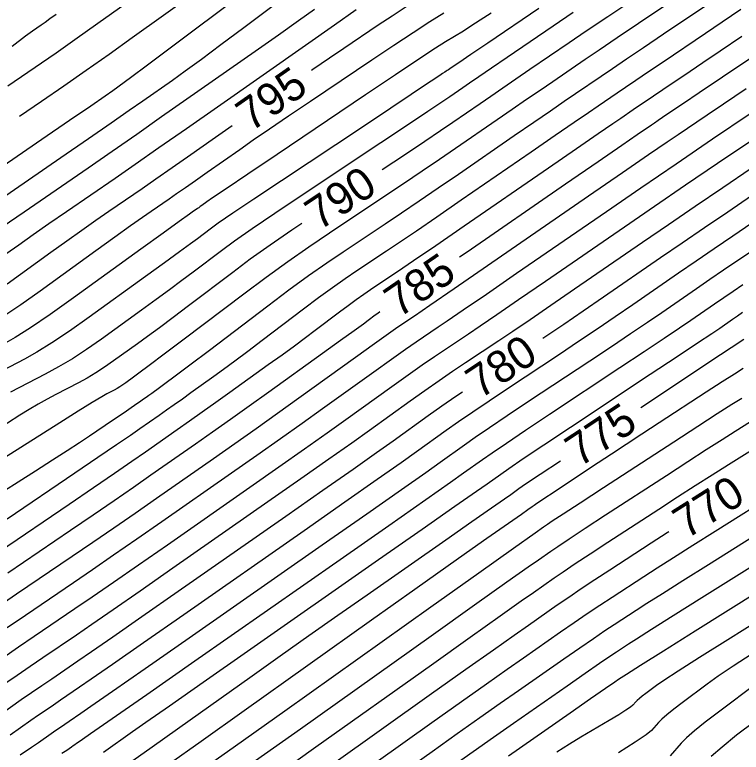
# Model space of a CAD drawing. Extents: x 2079879 to 2092887, y 778083 to 784051.
# Drawn here: x 2084522.6 to 2084585.7, y 781189.1 to 781253.2 of the extents above; entities that cross this region are included whole.
import ezdxf

# ---------------------------------------------------------------- set-up
doc = ezdxf.new("R2010")
doc.units = 0
doc.layers.add('DT_X_Contour_Major', color=7, linetype='Continuous')
doc.layers.add('DT_X_Contour_Minor', color=7, linetype='Continuous')

msp = doc.modelspace()

# ---------------------------------------------------------------- linework, layer by layer
at = {"layer": 'DT_X_Contour_Major'}
for points in [[(2084538.211, 781255.129), (2084532.768, 781251.231), (2084530.745, 781249.789), (2084528.757, 781248.387), (2084526.805, 781247.025), (2084524.887, 781245.702), (2084522.969, 781244.387)], [(2084576.341, 781254.591), (2084574.085, 781253.065), (2084572.219, 781251.8), (2084570.743, 781250.797), (2084567.327, 781248.469), (2084566.096, 781247.629), (2084564.961, 781246.854), (2084563.925, 781246.144), (2084562.987, 781245.498), (2084560.614, 781243.864), (2084559.565, 781243.147), (2084558.195, 781242.223), (2084556.505, 781241.091), (2084554.496, 781239.752), (2084554.491, 781239.749)], [(2084594.669, 781254.961), (2084586.708, 781249.594), (2084584.046, 781247.799), (2084582.028, 781246.439), (2084580.657, 781245.514), (2084579.93, 781245.024), (2084578.853, 781244.298), (2084578.477, 781244.044), (2084578.157, 781243.827), (2084577.892, 781243.647), (2084577.682, 781243.505), (2084577.197, 781243.174), (2084576.636, 781242.789), (2084575.319, 781241.883), (2084573.246, 781240.454), (2084570.415, 781238.504), (2084561.859, 781232.609), (2084561.215, 781232.165)], [(2084611.07, 781254.745), (2084608.274, 781252.74), (2084607.173, 781251.948), (2084605.967, 781251.077), (2084604.656, 781250.126), (2084603.241, 781249.096), (2084599.326, 781246.242), (2084597.779, 781245.129), (2084596.074, 781243.929), (2084594.21, 781242.642), (2084592.187, 781241.268), (2084586.582, 781237.488), (2084584.512, 781236.088), (2084582.503, 781234.724), (2084580.557, 781233.394), (2084578.673, 781232.1), (2084573.731, 781228.695), (2084571.936, 781227.463), (2084570.257, 781226.32), (2084568.695, 781225.267), (2084568.44, 781225.097)], [(2084556.664, 781253.975), (2084555.338, 781253.122), (2084554.145, 781252.331), (2084551.141, 781250.306), (2084549.91, 781249.47), (2084548.469, 781248.479), (2084548.334, 781248.385)], [(2084541.448, 781243.574), (2084539.722, 781242.364), (2084537.868, 781241.067), (2084536.233, 781239.926), (2084534.818, 781238.943), (2084533.622, 781238.116), (2084530.727, 781236.123), (2084529.598, 781235.339), (2084528.384, 781234.485), (2084527.083, 781233.561), (2084525.697, 781232.565), (2084521.887, 781229.816)], [(2084547.501, 781235.091), (2084546.632, 781234.506), (2084544.737, 781233.197), (2084543.026, 781231.977), (2084541.498, 781230.845), (2084537.667, 781227.946), (2084536.313, 781226.925), (2084535.122, 781226.034), (2084534.094, 781225.273), (2084533.23, 781224.644), (2084531.145, 781223.139), (2084530.367, 781222.597), (2084529.6, 781222.1), (2084528.842, 781221.648), (2084528.094, 781221.241), (2084526.113, 781220.215), (2084525.361, 781219.815), (2084524.592, 781219.382), (2084523.804, 781218.917), (2084522.999, 781218.42), (2084520.828, 781217.052)], [(2084554.29, 781227.41), (2084554.105, 781227.274), (2084553.883, 781227.109), (2084553.271, 781226.645), (2084552.851, 781226.336), (2084552.051, 781225.756), (2084550.871, 781224.906), (2084549.311, 781223.784), (2084544.644, 781220.432), (2084542.932, 781219.206), (2084541.295, 781218.041), (2084539.734, 781216.938), (2084538.249, 781215.897), (2084534.389, 781213.202), (2084532.866, 781212.144), (2084531.195, 781210.992), (2084529.374, 781209.745), (2084527.403, 781208.403), (2084521.95, 781204.698)], [(2084585.925, 781225.016), (2084584.799, 781224.269), (2084582.963, 781223.051), (2084580.418, 781221.364), (2084576.974, 781219.081)], [(2084561.451, 781220.438), (2084560.893, 781220.058), (2084559.657, 781219.199), (2084558.481, 781218.364), (2084555.427, 781216.17), (2084553.986, 781215.144), (2084551.955, 781213.712), (2084549.333, 781211.873), (2084546.121, 781209.628), (2084536.769, 781203.099), (2084533.593, 781200.884), (2084531.08, 781199.136), (2084529.231, 781197.855), (2084528.045, 781197.041), (2084525.767, 781195.493), (2084524.903, 781194.904), (2084524.02, 781194.297), (2084523.117, 781193.671), (2084522.196, 781193.027), (2084519.711, 781191.285), (2084518.71, 781190.592), (2084517.569, 781189.82), (2084516.289, 781188.969)], [(2084569.974, 781214.439), (2084568.203, 781213.26), (2084566.951, 781212.421), (2084566.358, 781212.015), (2084565.655, 781211.51), (2084565.104, 781211.121), (2084563.979, 781210.332), (2084562.279, 781209.143), (2084560.004, 781207.555), (2084553.172, 781202.785), (2084550.626, 781201.004), (2084548.112, 781199.237), (2084545.63, 781197.485), (2084543.18, 781195.748), (2084536.689, 781191.133), (2084534.505, 781189.581), (2084532.824, 781188.386)], [(2084579.393, 781208.293), (2084579.259, 781208.207), (2084577.866, 781207.305), (2084574.274, 781204.969), (2084572.978, 781204.12), (2084571.784, 781203.326), (2084570.692, 781202.587), (2084569.7, 781201.902), (2084567.193, 781200.15), (2084565.962, 781199.285), (2084564.15, 781198.004), (2084561.757, 781196.307), (2084558.783, 781194.194), (2084550.077, 781188.005)], [(2084591.899, 781203.525), (2084584.532, 781198.9), (2084582.071, 781197.35), (2084580.216, 781196.17), (2084578.965, 781195.359), (2084578.318, 781194.917), (2084577.402, 781194.232), (2084577.089, 781193.993), (2084576.838, 781193.792), (2084576.649, 781193.628), (2084576.523, 781193.5), (2084576.267, 781193.21), (2084576.068, 781193.046), (2084575.661, 781192.773), (2084575.046, 781192.389), (2084574.223, 781191.896), (2084571.753, 781190.435), (2084570.766, 781189.832), (2084569.656, 781189.119)]]:
    msp.add_lwpolyline(points, dxfattribs=at)
at = {"layer": 'DT_X_Contour_Minor'}
for points in [[(2084545.551, 781257.468), (2084538.269, 781251.987), (2084535.833, 781250.156), (2084533.986, 781248.771), (2084532.729, 781247.833), (2084532.061, 781247.342), (2084531.065, 781246.629), (2084530.4, 781246.163), (2084529.152, 781245.3), (2084527.32, 781244.04), (2084524.906, 781242.382), (2084517.691, 781237.434)], [(2084548.153, 781256.39), (2084542.461, 781252.106), (2084540.472, 781250.616), (2084538.775, 781249.357), (2084537.369, 781248.331), (2084536.255, 781247.536), (2084533.671, 781245.726), (2084532.501, 781244.909), (2084530.927, 781243.818), (2084528.95, 781242.453), (2084526.57, 781240.813), (2084519.686, 781236.072)], [(2084583.912, 781254.906), (2084578.934, 781251.546), (2084577.196, 781250.372), (2084575.714, 781249.37), (2084574.488, 781248.539), (2084573.518, 781247.88), (2084571.275, 781246.351), (2084570.312, 781245.693), (2084569.105, 781244.865), (2084567.653, 781243.868), (2084565.958, 781242.701), (2084561.112, 781239.362), (2084559.351, 781238.152), (2084557.702, 781237.029), (2084556.166, 781235.991), (2084554.742, 781235.038), (2084551.095, 781232.613), (2084549.66, 781231.637), (2084548.09, 781230.528), (2084546.386, 781229.285), (2084544.548, 781227.91), (2084539.467, 781224.064), (2084537.767, 781222.779), (2084536.48, 781221.809), (2084535.606, 781221.153), (2084535.143, 781220.812), (2084534.461, 781220.322), (2084534.21, 781220.143), (2084533.971, 781219.972), (2084533.743, 781219.811), (2084533.525, 781219.659), (2084532.961, 781219.264), (2084532.682, 781219.071), (2084532.268, 781218.788), (2084531.72, 781218.414), (2084531.038, 781217.951), (2084529.04, 781216.593), (2084528.185, 781216.022), (2084527.121, 781215.329), (2084525.846, 781214.512), (2084524.362, 781213.572), (2084520.124, 781210.901)], [(2084568.085, 781253.794), (2084563.655, 781250.775), (2084562.195, 781249.781), (2084561.14, 781249.063), (2084560.49, 781248.622), (2084560.244, 781248.457), (2084560.126, 781248.386), (2084560.053, 781248.339), (2084559.921, 781248.252), (2084559.732, 781248.126), (2084559.485, 781247.959), (2084558.749, 781247.463), (2084558.173, 781247.078), (2084556.998, 781246.295), (2084555.225, 781245.115), (2084552.852, 781243.537), (2084545.726, 781238.798), (2084543.335, 781237.204), (2084541.508, 781235.975), (2084540.245, 781235.11), (2084539.545, 781234.611), (2084538.429, 781233.767), (2084537.834, 781233.324), (2084536.884, 781232.63), (2084535.58, 781231.684), (2084533.922, 781230.486), (2084529.029, 781226.955), (2084527.301, 781225.733), (2084525.785, 781224.715), (2084524.482, 781223.9), (2084523.392, 781223.289), (2084520.769, 781221.931)], [(2084548.598, 781253.704), (2084547.207, 781252.7), (2084545.486, 781251.477), (2084543.434, 781250.033), (2084537.522, 781245.89), (2084535.321, 781244.351), (2084533.154, 781242.842), (2084531.021, 781241.363), (2084528.921, 781239.914), (2084523.367, 781236.089), (2084521.462, 781234.775)], [(2084578.961, 781253.962), (2084576.769, 781252.481), (2084574.899, 781251.217), (2084573.353, 781250.169), (2084572.131, 781249.338), (2084569.301, 781247.41), (2084568.204, 781246.661), (2084567.033, 781245.86), (2084565.789, 781245.006), (2084564.472, 781244.099), (2084560.863, 781241.613), (2084559.458, 781240.65), (2084557.949, 781239.626), (2084556.336, 781238.541), (2084554.619, 781237.395), (2084549.902, 781234.259), (2084548.111, 781233.046), (2084546.276, 781231.759), (2084544.397, 781230.397), (2084542.474, 781228.962), (2084537.286, 781225.036), (2084535.552, 781223.725), (2084534.241, 781222.736), (2084533.351, 781222.068), (2084532.884, 781221.723), (2084532.202, 781221.23), (2084531.948, 781221.053), (2084531.697, 781220.891), (2084531.449, 781220.743), (2084531.204, 781220.61), (2084530.557, 781220.274), (2084530.119, 781220.023), (2084529.292, 781219.519), (2084528.076, 781218.763), (2084526.471, 781217.754), (2084521.672, 781214.73)], [(2084532.141, 781254.164), (2084529.779, 781252.477), (2084527.78, 781251.057), (2084526.143, 781249.906), (2084524.869, 781249.022), (2084521.953, 781247.023)], [(2084563.943, 781253.381), (2084562.998, 781252.753), (2084562.198, 781252.234), (2084561.543, 781251.825), (2084559.989, 781250.88), (2084559.119, 781250.327), (2084557.672, 781249.375), (2084555.648, 781248.025), (2084553.048, 781246.277), (2084545.347, 781241.085), (2084542.8, 781239.367), (2084540.935, 781238.108), (2084539.752, 781237.308), (2084539.25, 781236.966), (2084538.822, 781236.666), (2084538.671, 781236.56), (2084538.537, 781236.467), (2084538.421, 781236.387), (2084538.324, 781236.319), (2084538.087, 781236.156), (2084537.734, 781235.904), (2084536.854, 781235.271), (2084535.447, 781234.257), (2084533.511, 781232.861), (2084527.647, 781228.63), (2084525.619, 781227.187), (2084523.93, 781226.033), (2084522.583, 781225.167), (2084521.575, 781224.59)], [(2084559.853, 781253.375), (2084558.621, 781252.609), (2084557.168, 781251.675), (2084555.493, 781250.574), (2084553.597, 781249.304), (2084548.244, 781245.696), (2084546.355, 781244.419), (2084544.702, 781243.294), (2084543.285, 781242.321), (2084542.105, 781241.5), (2084539.272, 781239.515), (2084538.269, 781238.813), (2084537.385, 781238.197), (2084536.62, 781237.665), (2084535.973, 781237.218), (2084534.407, 781236.139), (2084533.666, 781235.622), (2084532.619, 781234.878), (2084531.265, 781233.909), (2084529.604, 781232.713), (2084524.767, 781229.223), (2084523.094, 781228.033), (2084521.701, 781227.081)], [(2084552.236, 781253.664), (2084550.353, 781252.347), (2084547.815, 781250.569), (2084540.172, 781245.214), (2084537.467, 781243.32), (2084535.081, 781241.656), (2084533.016, 781240.221), (2084531.272, 781239.015), (2084527.047, 781236.106), (2084525.53, 781235.057), (2084524.148, 781234.093), (2084522.902, 781233.213), (2084521.79, 781232.417)], [(2084585.655, 781253.684), (2084584.042, 781252.595), (2084582.585, 781251.612), (2084578.907, 781249.13), (2084577.623, 781248.263), (2084576.528, 781247.522), (2084575.622, 781246.908), (2084574.906, 781246.421), (2084573.249, 781245.292), (2084572.42, 781244.725), (2084571.176, 781243.871), (2084569.517, 781242.73), (2084567.444, 781241.302), (2084561.361, 781237.111), (2084559.244, 781235.655), (2084557.456, 781234.432), (2084555.996, 781233.44), (2084554.865, 781232.681), (2084552.287, 781230.967), (2084551.273, 781230.277), (2084550.163, 781229.493), (2084548.959, 781228.615), (2084547.66, 781227.643), (2084544.068, 781224.925), (2084542.795, 781223.965), (2084541.671, 781223.125), (2084540.694, 781222.404), (2084539.866, 781221.803), (2084537.855, 781220.359), (2084537.118, 781219.83), (2084536.412, 781219.329), (2084535.74, 781218.853), (2084535.1, 781218.405), (2084533.437, 781217.244), (2084532.615, 781216.675), (2084531.397, 781215.841), (2084529.784, 781214.74), (2084527.774, 781213.374), (2084521.887, 781209.375)], [(2084571.084, 781253.431), (2084569.355, 781252.255), (2084565.354, 781249.529), (2084563.987, 781248.597), (2084562.89, 781247.848), (2084562.061, 781247.281), (2084561.501, 781246.897), (2084560.365, 781246.115), (2084559.672, 781245.644), (2084558.441, 781244.82), (2084556.675, 781243.641), (2084554.372, 781242.109), (2084547.517, 781237.551), (2084545.152, 781235.967), (2084543.197, 781234.636), (2084541.654, 781233.556), (2084540.521, 781232.728), (2084538.048, 781230.857), (2084537.073, 781230.125), (2084536.003, 781229.332), (2084534.837, 781228.479), (2084533.576, 781227.565), (2084530.087, 781225.047), (2084528.801, 781224.148), (2084527.559, 781223.338), (2084526.362, 781222.619), (2084525.209, 781221.989), (2084522.195, 781220.428)], [(2084526.139, 781253.249), (2084525.614, 781252.876), (2084525.184, 781252.574), (2084524.85, 781252.342), (2084524.084, 781251.817), (2084523.502, 781251.382), (2084522.33, 781250.471)], [(2084585.735, 781251.338), (2084583.842, 781250.062), (2084582.349, 781249.055), (2084581.257, 781248.318), (2084578.88, 781246.714), (2084578.05, 781246.153), (2084577.342, 781245.674), (2084576.757, 781245.278), (2084576.294, 781244.963), (2084575.223, 781244.233), (2084574.528, 781243.757), (2084573.248, 781242.877), (2084571.382, 781241.592), (2084568.929, 781239.903), (2084561.61, 781234.86), (2084559.137, 781233.158), (2084557.209, 781231.835), (2084555.826, 781230.89), (2084554.988, 781230.325), (2084553.479, 781229.321), (2084552.886, 781228.918), (2084552.237, 781228.459), (2084551.532, 781227.945), (2084550.771, 781227.376), (2084548.669, 781225.785), (2084547.823, 781225.151), (2084546.861, 781224.441), (2084545.783, 781223.655), (2084544.589, 781222.793), (2084541.25, 781220.395), (2084540.025, 781219.518), (2084538.854, 781218.685), (2084537.737, 781217.896), (2084536.674, 781217.151), (2084533.913, 781215.223), (2084532.721, 781214.396), (2084531.218, 781213.363), (2084529.402, 781212.122), (2084527.275, 781210.675), (2084521.186, 781206.539)], [(2084586.118, 781246.797), (2084584.15, 781245.47), (2084582.723, 781244.508), (2084581.839, 781243.912), (2084580.204, 781242.809), (2084579.256, 781242.164), (2084577.641, 781241.057), (2084575.357, 781239.487), (2084572.405, 781237.454), (2084563.642, 781231.417), (2084560.744, 781229.421), (2084558.624, 781227.962), (2084557.28, 781227.039), (2084556.713, 781226.653), (2084556.238, 781226.338), (2084555.851, 781226.069), (2084555.046, 781225.496), (2084553.822, 781224.621), (2084552.18, 781223.443), (2084547.244, 781219.898), (2084545.392, 781218.573), (2084543.538, 781217.255), (2084541.682, 781215.945), (2084539.823, 781214.643), (2084534.865, 781211.181), (2084533.012, 781209.892), (2084531.172, 781208.62), (2084529.345, 781207.367), (2084527.532, 781206.13), (2084522.713, 781202.857), (2084520.886, 781201.611)], [(2084586.469, 781244.628), (2084583.197, 781242.417), (2084580.024, 781240.261), (2084576.949, 781238.16), (2084573.972, 781236.116), (2084566.164, 781230.737), (2084563.542, 781228.932), (2084561.532, 781227.552), (2084560.134, 781226.596), (2084559.347, 781226.065), (2084558.066, 781225.216), (2084557.436, 781224.787), (2084556.508, 781224.137), (2084555.281, 781223.266), (2084553.755, 781222.173), (2084549.29, 781218.966), (2084547.541, 781217.716), (2084545.642, 781216.369), (2084543.595, 781214.927), (2084541.398, 781213.389), (2084535.341, 781209.161), (2084533.157, 781207.64), (2084531.149, 781206.249), (2084529.317, 781204.989), (2084527.66, 781203.858), (2084523.477, 781201.016), (2084521.89, 781199.934)], [(2084586.507, 781242.248), (2084583.636, 781240.307), (2084580.85, 781238.415), (2084578.151, 781236.572), (2084575.539, 781234.777), (2084568.686, 781230.056), (2084566.34, 781228.442), (2084564.44, 781227.141), (2084562.987, 781226.153), (2084561.981, 781225.478), (2084559.893, 781224.094), (2084559.021, 781223.505), (2084557.969, 781222.777), (2084556.739, 781221.91), (2084555.331, 781220.904), (2084551.335, 781218.034), (2084549.689, 781216.859), (2084547.746, 781215.484), (2084545.508, 781213.909), (2084542.972, 781212.136), (2084535.817, 781207.14), (2084533.302, 781205.388), (2084531.126, 781203.878), (2084529.288, 781202.611), (2084527.788, 781201.586), (2084524.24, 781199.175), (2084522.894, 781198.257), (2084521.519, 781197.311)], [(2084586.545, 781239.868), (2084584.074, 781238.198), (2084581.677, 781236.569), (2084579.354, 781234.983), (2084577.106, 781233.439), (2084571.208, 781229.376), (2084569.138, 781227.953), (2084567.349, 781226.731), (2084565.841, 781225.71), (2084564.615, 781224.89), (2084561.72, 781222.971), (2084560.605, 781222.223), (2084559.431, 781221.418), (2084558.198, 781220.554), (2084556.906, 781219.634), (2084553.381, 781217.102), (2084551.838, 781216.002), (2084549.851, 781214.598), (2084547.42, 781212.891), (2084544.547, 781210.882), (2084536.293, 781205.119), (2084533.448, 781203.136), (2084531.103, 781201.507), (2084529.26, 781200.233), (2084527.917, 781199.313), (2084525.004, 781197.334), (2084523.899, 781196.581), (2084522.769, 781195.804), (2084521.615, 781195.003)], [(2084586.62, 781235.108), (2084584.95, 781233.979), (2084583.33, 781232.878), (2084581.759, 781231.806), (2084580.239, 781230.762), (2084576.253, 781228.015), (2084574.734, 781226.974), (2084573.165, 781225.91), (2084571.548, 781224.824), (2084569.882, 781223.715), (2084565.375, 781220.727), (2084563.775, 781219.66), (2084562.355, 781218.698), (2084561.116, 781217.843), (2084560.056, 781217.094), (2084557.472, 781215.238), (2084556.135, 781214.287), (2084554.059, 781212.826), (2084551.246, 781210.855), (2084547.696, 781208.374), (2084537.244, 781201.078), (2084533.738, 781198.631), (2084531.058, 781196.764), (2084529.203, 781195.477), (2084528.174, 781194.769), (2084526.531, 781193.653), (2084525.908, 781193.227), (2084525.271, 781192.789), (2084524.62, 781192.338), (2084523.955, 781191.873), (2084522.163, 781190.617)], [(2084586.658, 781232.728), (2084585.388, 781231.869), (2084584.156, 781231.032), (2084582.962, 781230.217), (2084581.806, 781229.423), (2084578.775, 781227.335), (2084577.531, 781226.484), (2084576.074, 781225.5), (2084574.402, 781224.38), (2084572.516, 781223.127), (2084567.202, 781219.605), (2084565.36, 781218.378), (2084563.817, 781217.339), (2084562.574, 781216.488), (2084561.632, 781215.824), (2084559.518, 781214.306), (2084558.283, 781213.43), (2084556.163, 781211.941), (2084553.159, 781209.837), (2084549.27, 781207.12), (2084537.72, 781199.057), (2084533.883, 781196.379), (2084531.035, 781194.393), (2084529.174, 781193.099), (2084528.302, 781192.496), (2084527.294, 781191.812), (2084526.912, 781191.551), (2084526.521, 781191.282), (2084526.122, 781191.005), (2084525.714, 781190.72), (2084524.615, 781189.95), (2084524.008, 781189.537), (2084523.013, 781188.876)], [(2084585.826, 781229.76), (2084584.982, 781229.187), (2084584.165, 781228.628), (2084583.373, 781228.085), (2084581.297, 781226.654), (2084580.329, 781225.995), (2084578.982, 781225.089), (2084577.256, 781223.937), (2084575.15, 781222.539), (2084569.03, 781218.482), (2084566.945, 781217.096), (2084565.279, 781215.979), (2084564.033, 781215.132), (2084563.207, 781214.555), (2084561.564, 781213.374), (2084560.431, 781212.573), (2084558.268, 781211.055), (2084555.072, 781208.819), (2084550.845, 781205.867), (2084538.196, 781197.036), (2084534.029, 781194.127), (2084531.012, 781192.022), (2084529.146, 781190.721), (2084528.431, 781190.224), (2084528.058, 781189.971), (2084527.916, 781189.874), (2084527.772, 781189.775), (2084527.624, 781189.672), (2084527.473, 781189.567), (2084527.067, 781189.282), (2084526.658, 781189.009)], [(2084585.809, 781227.341), (2084585.367, 781227.04), (2084584.94, 781226.746), (2084583.819, 781225.974), (2084583.127, 781225.506), (2084581.89, 781224.679), (2084580.109, 781223.494), (2084577.784, 781221.952), (2084570.857, 781217.36), (2084568.529, 781215.814), (2084566.741, 781214.62), (2084565.492, 781213.777), (2084564.782, 781213.285), (2084563.609, 781212.442), (2084562.69, 781211.793), (2084560.811, 781210.476), (2084557.973, 781208.491), (2084554.176, 781205.839), (2084542.771, 781197.877), (2084538.94, 781195.202), (2084536.001, 781193.146), (2084533.952, 781191.71), (2084532.795, 781190.894), (2084530.26, 781189.092)], [(2084585.851, 781222.497), (2084585.091, 781222.007), (2084584.02, 781221.313), (2084582.639, 781220.415), (2084578.541, 781217.749), (2084577.058, 781216.782), (2084575.684, 781215.883), (2084574.417, 781215.051), (2084573.259, 781214.285), (2084570.315, 781212.334), (2084569.338, 781211.686), (2084568.616, 781211.205), (2084568.147, 781210.892), (2084567.933, 781210.745), (2084567.7, 781210.578), (2084567.518, 781210.45), (2084567.146, 781210.189), (2084566.584, 781209.796), (2084565.832, 781209.27), (2084563.573, 781207.693), (2084562.312, 781206.807), (2084560.224, 781205.329), (2084557.308, 781203.26), (2084553.565, 781200.601), (2084542.48, 781192.721), (2084538.751, 781190.07), (2084535.881, 781188.029)], [(2084585.724, 781219.891), (2084584.868, 781219.348), (2084583.602, 781218.533), (2084581.924, 781217.447), (2084579.834, 781216.089), (2084573.715, 781212.108), (2084571.69, 781210.79), (2084570.205, 781209.821), (2084569.259, 781209.202), (2084568.854, 781208.932), (2084568.492, 781208.679), (2084567.779, 781208.174), (2084565.91, 781206.847), (2084562.887, 781204.698), (2084558.708, 781201.727), (2084546.024, 781192.711), (2084541.734, 781189.661), (2084538.375, 781187.273)], [(2084587.829, 781218.683), (2084585.147, 781216.999), (2084584.02, 781216.285), (2084582.649, 781215.408), (2084581.035, 781214.367), (2084579.178, 781213.161), (2084573.901, 781209.728), (2084572.119, 781208.567), (2084570.731, 781207.656), (2084569.737, 781206.997), (2084569.136, 781206.589), (2084568.059, 781205.836), (2084567.173, 781205.211), (2084565.324, 781203.899), (2084562.51, 781201.901), (2084558.733, 781199.216), (2084547.375, 781191.143), (2084543.482, 781188.375)], [(2084588.201, 781216.386), (2084584.57, 781214.106), (2084583.171, 781213.223), (2084581.697, 781212.283), (2084580.147, 781211.287), (2084578.522, 781210.233), (2084574.088, 781207.349), (2084572.549, 781206.343), (2084571.258, 781205.491), (2084570.214, 781204.792), (2084569.418, 781204.246), (2084567.626, 781202.993), (2084566.568, 781202.248), (2084564.737, 781200.951), (2084562.134, 781199.104), (2084558.758, 781196.705), (2084548.726, 781189.574), (2084545.23, 781187.089)], [(2084588.945, 781211.792), (2084583.417, 781208.321), (2084581.474, 781207.099), (2084579.792, 781206.034), (2084578.37, 781205.127), (2084577.209, 781204.377), (2084574.461, 781202.589), (2084573.408, 781201.897), (2084572.311, 781201.161), (2084571.169, 781200.382), (2084569.983, 781199.559), (2084566.76, 781197.307), (2084565.357, 781196.322), (2084563.564, 781195.056), (2084561.381, 781193.51), (2084558.808, 781191.683), (2084551.428, 781186.437)], [(2084589.317, 781209.495), (2084582.84, 781205.429), (2084580.625, 781204.036), (2084578.839, 781202.909), (2084577.482, 781202.047), (2084576.553, 781201.449), (2084574.647, 781200.209), (2084573.837, 781199.674), (2084572.837, 781198.996), (2084571.646, 781198.177), (2084570.265, 781197.216), (2084566.327, 781194.464), (2084564.751, 781193.359), (2084562.977, 781192.109), (2084561.004, 781190.713), (2084558.833, 781189.172), (2084552.779, 781184.868)], [(2084589.689, 781207.198), (2084582.263, 781202.536), (2084579.777, 781200.974), (2084577.887, 781199.784), (2084576.593, 781198.967), (2084575.897, 781198.521), (2084574.834, 781197.83), (2084574.267, 781197.45), (2084573.364, 781196.831), (2084572.124, 781195.972), (2084570.547, 781194.872), (2084565.894, 781191.62), (2084564.146, 781190.396), (2084562.39, 781189.161), (2084560.628, 781187.916)], [(2084590.061, 781204.902), (2084581.686, 781199.644), (2084578.928, 781197.912), (2084576.934, 781196.66), (2084575.705, 781195.887), (2084575.24, 781195.593), (2084575.02, 781195.45), (2084574.697, 781195.227), (2084573.89, 781194.666), (2084572.601, 781193.767), (2084570.829, 781192.529), (2084565.461, 781188.777)], [(2084586.624, 781197.671), (2084584.992, 781196.61), (2084583.689, 781195.732), (2084582.716, 781195.036), (2084580.558, 781193.424), (2084579.822, 781192.862), (2084579.232, 781192.388), (2084578.788, 781192.002), (2084578.49, 781191.702), (2084577.889, 781191.019), (2084577.419, 781190.634), (2084576.461, 781189.99), (2084575.014, 781189.088)], [(2084587.113, 781195.155), (2084583.715, 781192.615), (2084582.556, 781191.732), (2084581.626, 781190.985), (2084580.927, 781190.376), (2084580.457, 781189.904), (2084579.51, 781188.828)], [(2084586.872, 781191.807), (2084585.289, 781190.601), (2084584.02, 781189.582), (2084583.065, 781188.75)]]:
    msp.add_lwpolyline(points, dxfattribs=at)

# ---------------------------------------------------------------- texts
at = {"layer": 'DT_X_Contour_Major'}
for s, rotation, p in [('795', 34.94194, (2084543.079, 781243.012)), ('790', 33.67652, (2084549.018, 781234.425)), ('785', 34.47862, (2084555.94, 781226.838)), ('780', 33.68836, (2084562.985, 781219.786)), ('775', 33.55058, (2084571.629, 781213.858)), ('770', 32.31075, (2084580.927, 781207.621))]:
    msp.add_text(s, height=2.8, rotation=rotation, dxfattribs=at).set_placement(p)

doc.saveas('drawing.dxf')
